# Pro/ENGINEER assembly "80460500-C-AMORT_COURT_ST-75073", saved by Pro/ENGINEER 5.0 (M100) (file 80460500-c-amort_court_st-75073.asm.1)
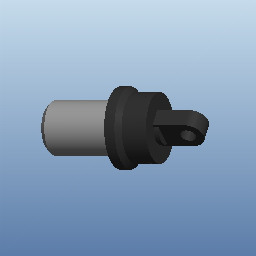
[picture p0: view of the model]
Units: millimeter Newton Second (mmNs); MM, TONNE, HOURS

Other components: 80460500-C-AMORT_COURT_ST-75042, 80160500-BOUCHON_AMORT-STD_01

Other named items: A-DROITE, A-DESSUS, A-FACE, A-R0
